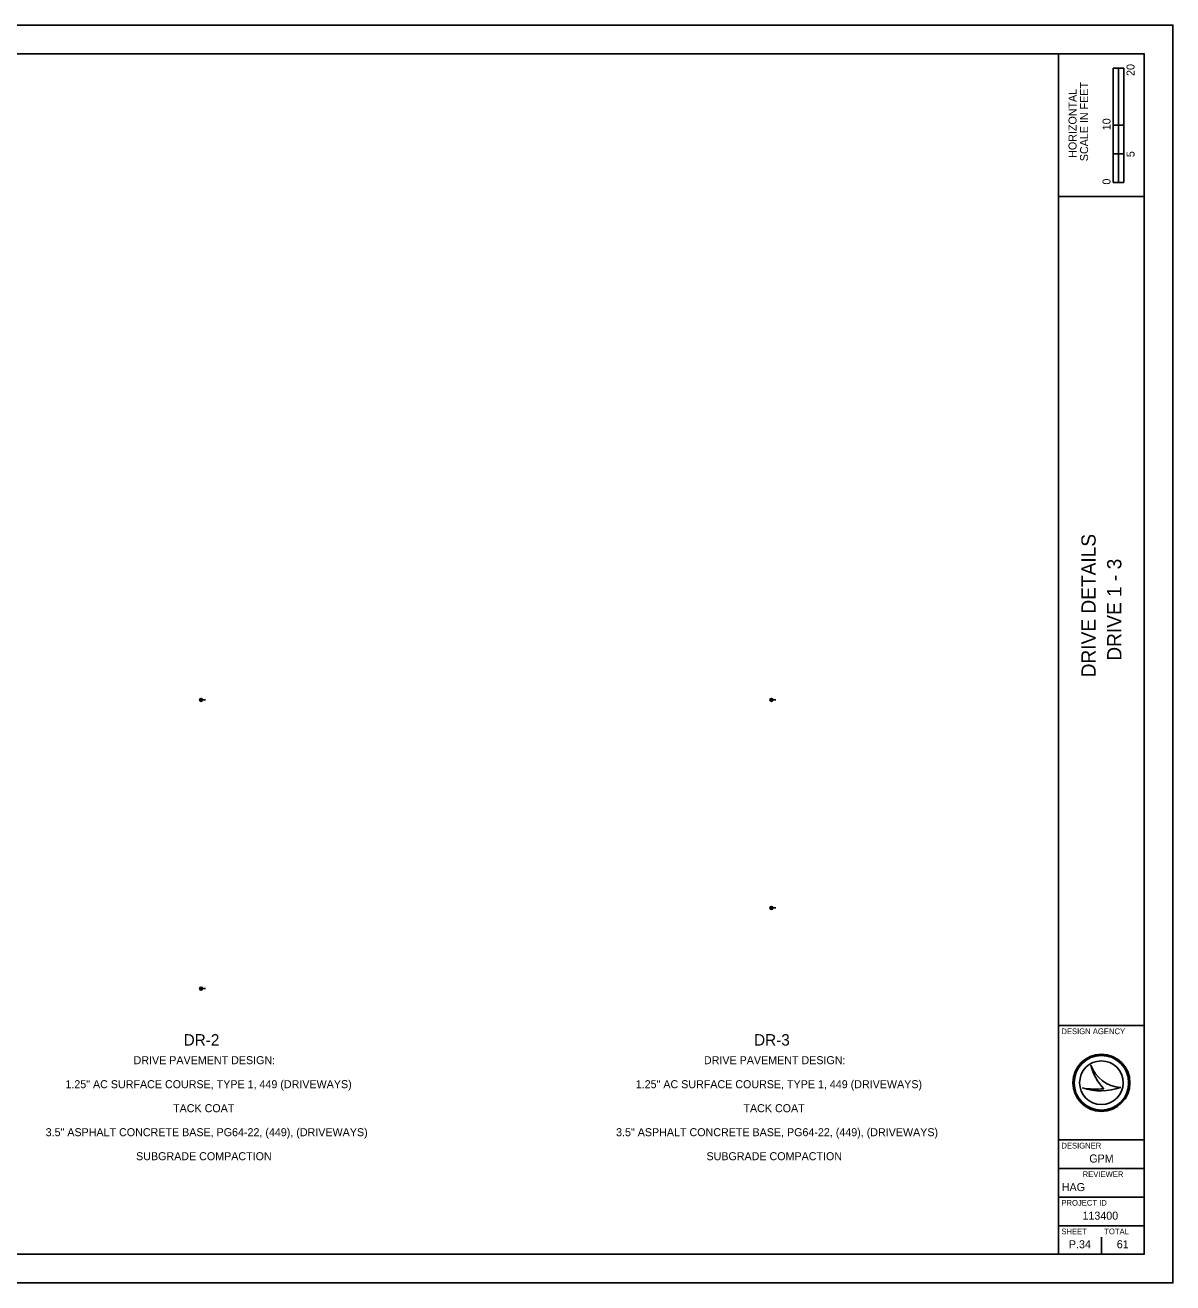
# Model space of a CAD drawing. Extents: x -2.7 to 34, y 0 to 22.
# Drawn here: x 13.92 to 34, y 0 to 22 of the extents above; entities that cross this region are included whole.
import ezdxf

# ---------------------------------------------------------------- set-up
doc = ezdxf.new("R2010")
doc.units = 0
for name, color, linetype in [('_CIVIL_CONSTRUCTION', 7, 'Continuous'), ('Default', 7, 'Continuous'), ('PF_X_Ground_Line', 7, 'Continuous'), ('UT_X_Sanitary_Line', 7, 'Continuous'), ('UT_X_Water', 7, 'Continuous')]:
    doc.layers.add(name, color=color, linetype=linetype)

msp = doc.modelspace()

# ---------------------------------------------------------------- linework, layer by layer
at = {"layer": '_CIVIL_CONSTRUCTION'}
for p, q in [((32, 0.5), (32, 21.5)), ((32, 19), (33.5, 19)), ((32, 4.5), (33.5, 4.5)), ((32, 2.5), (33.5, 2.5)), ((32, 2), (33.5, 2)), ((32, 1.5), (33.5, 1.5)), ((32, 1), (33.5, 1))]:
    msp.add_line(p, q, dxfattribs=at)
msp.add_lwpolyline([(1.5, 21.5), (33.5, 21.5), (33.5, 0.5), (1.5, 0.5)], close=True, dxfattribs=at)
at = {"layer": 'Default'}
for p, q in [((16.974, 10.198), (17.026, 10.198)), ((17, 10.198), (17.074, 10.198)), ((26.952, 10.198), (27.004, 10.198)), ((26.978, 10.198), (27.053, 10.198)), ((26.952, 6.557), (27.004, 6.557)), ((26.978, 6.557), (27.056, 6.557)), ((16.974, 5.146), (17.026, 5.146)), ((17, 5.146), (17.077, 5.146))]:
    msp.add_line(p, q, dxfattribs=at)
for centre in [(17, 10.198), (26.978, 10.198), (26.978, 6.557), (17, 5.146)]:
    msp.add_circle(centre, 0.026, dxfattribs=at)
at = {"layer": 'PF_X_Ground_Line'}
msp.add_lwpolyline([(0, 0), (34, 0), (34, 22), (0, 22)], close=True, dxfattribs=at)
at = {"layer": 'UT_X_Sanitary_Line'}
for p, q in [((32.957, 19.25), (32.957, 21.25)), ((33.144, 21.25), (32.957, 21.25)), ((32.957, 20.25), (32.957, 21.25)), ((32.957, 21.25), (33.05, 21.25)), ((33.05, 21.25), (33.051, 21.25)), ((33.051, 21.25), (33.051, 20.25)), ((33.144, 21.25), (33.144, 19.25)), ((33.051, 20.25), (32.957, 20.25)), ((33.143, 20.25), (33.05, 20.25)), ((33.05, 20.25), (33.05, 19.75)), ((33.143, 19.75), (33.143, 20.25)), ((33.05, 19.75), (32.957, 19.75)), ((32.957, 19.75), (32.957, 19.25)), ((33.05, 19.25), (33.05, 19.75)), ((33.05, 19.75), (33.143, 19.75)), ((33.144, 19.25), (32.957, 19.25)), ((32.957, 19.25), (33.05, 19.25)), ((32.567, 3.81), (32.567, 3.81)), ((32.417, 3.41), (32.417, 3.41)), ((32.75, 3.5), (32.75, 3.5)), ((33.087, 3.419), (33.087, 3.419)), ((32.375, 0.675), (32.375, 0.675)), ((32.75, 0.5), (32.75, 0.8))]:
    msp.add_line(p, q, dxfattribs=at)
for radius in [0.5, 0.477, 0.477, 0.382]:
    msp.add_circle((32.75, 3.5), radius, dxfattribs=at)
for centre, radius, start, end in [((33.116, 3.998), 0.58, 198.9257, 198.9319), ((33.347, 3.97), 0.796, 191.6379, 191.6421), ((33.116, 3.998), 0.58, 198.9319, 267.1657), ((33.347, 3.97), 0.796, 191.6421, 226.0947), ((32.739, 4.37), 1.013, 251.4576, 290.0832), ((32.648, 4.654), 1.266, 259.4964, 259.4995), ((32.739, 4.37), 1.013, 251.4527, 251.4576), ((32.648, 4.654), 1.266, 259.4995, 276.6672)]:
    msp.add_arc(centre, radius, start, end, dxfattribs=at)

# ---------------------------------------------------------------- texts
at = {"layer": 'Default'}
for s, p in [('P.31', (16.996, 10.188)), ('3', (16.999, 10.204)), ('CLP_Drive2 - Plan 2', (17.032, 10.204)), ('1:10', (17.032, 10.188)), ('P.31', (26.974, 10.188)), ('5', (26.977, 10.204)), ('CLP_Drive3 - Plan 3', (27.011, 10.204)), ('1:10', (27.011, 10.188)), ('P.31', (26.974, 6.547)), ('6', (26.977, 6.564)), ('CLP_Drive3 - Profile 1', (27.011, 6.564)), ('1:10', (27.011, 6.547)), ('P.31', (16.996, 5.137)), ('4', (16.999, 5.153)), ('CLP_Drive2 - Profile 1', (17.032, 5.153)), ('1:10', (17.032, 5.137))]:
    msp.add_text(s, height=0.00328, dxfattribs=at).set_placement(p)
at = {"layer": 'UT_X_Sanitary_Line'}
for s, height, p in [('20', 0.14, (33.33, 21.112)), ('SCALE IN FEET', 0.14, (32.517, 19.621)), ('HORIZONTAL', 0.14, (32.315, 19.679)), ('10', 0.14, (32.91, 20.162)), ('5', 0.14, (33.33, 19.691)), ('0', 0.14, (32.91, 19.211)), ('DRIVE DETAILS', 0.25, (32.65, 10.592)), ('DRIVE 1 - 3', 0.25, (33.1, 10.883))]:
    msp.add_text(s, height=height, rotation=90, dxfattribs=at).set_placement(p)
for s, height, p in [('DESIGN AGENCY', 0.1, (32.05, 4.35)), ('DESIGNER', 0.1, (32.05, 2.35)), ('GPM', 0.14, (32.538, 2.105)), ('REVIEWER', 0.1, (32.422, 1.85)), ('HAG', 0.14, (32.057, 1.605)), ('PROJECT ID', 0.1, (32.05, 1.35)), ('113400', 0.14, (32.419, 1.105)), ('SHEET', 0.1, (32.05, 0.85)), ('TOTAL', 0.1, (32.8, 0.85)), ('P.34', 0.14, (32.182, 0.605)), ('61', 0.14, (33.019, 0.605))]:
    msp.add_text(s, height=height, dxfattribs=at).set_placement(p)
at = {"layer": 'UT_X_Water'}
for s, height, p in [('DR-2', 0.2, (16.695, 4.15)), ('DR-3', 0.2, (26.674, 4.15)), ('DRIVE PAVEMENT DESIGN:', 0.14, (15.819, 3.825)), ('DRIVE PAVEMENT DESIGN:', 0.14, (25.797, 3.825)), ('1.25" AC SURFACE COURSE, TYPE 1, 449 (DRIVEWAYS)', 0.14, (14.626, 3.405)), ('1.25" AC SURFACE COURSE, TYPE 1, 449 (DRIVEWAYS)', 0.14, (24.604, 3.405)), ('TACK COAT', 0.14, (16.51, 2.985)), ('TACK COAT', 0.14, (26.488, 2.985)), ('3.5" ASPHALT CONCRETE BASE, PG64-22, (449), (DRIVEWAYS)', 0.14, (14.281, 2.565)), ('3.5" ASPHALT CONCRETE BASE, PG64-22, (449), (DRIVEWAYS)', 0.14, (24.26, 2.565)), ('SUBGRADE COMPACTION', 0.14, (15.863, 2.145)), ('SUBGRADE COMPACTION', 0.14, (25.841, 2.145))]:
    msp.add_text(s, height=height, dxfattribs=at).set_placement(p)

doc.saveas('drawing.dxf')
